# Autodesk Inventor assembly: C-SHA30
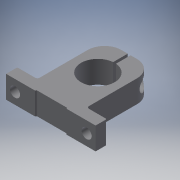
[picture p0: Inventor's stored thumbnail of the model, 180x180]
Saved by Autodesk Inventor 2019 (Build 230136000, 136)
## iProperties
Category: PARTsolutions
Company: MISUMI
Created: 2022-11
Part Number: C-SHA30
Catalog Web Link: www.cadenas.de
Description: C-SHA-Economy Shaft Supports - T-Shaped/Slit
Vendor: MISUMI
Document SubType Name: Assembly
Designer: psAdmin
Manufacturer: MISUMI
Mass: 49.6366 g
Surface Area: 148.895 cm^2
Volume: 49.6366 cm^3
Density: 1 g/cm^3
Title: C-SHA30
Author: Cadenas PARTsolutions
Comments: Economy Shaft Supports - T-Shaped/Slit
PSOL_IDENT_0: {$CADENAS_DATA/23d-libs/misumi/metric/02_shaft_supports/c_sha_asmtab.prj},167 {VTYP=3D},{STYP=ASSTAB
PSOL_IDENT_1: },{NB=C-SHA30},{LINA=C-SHA30},{NN=C-SHA},{DATE=04.10.2022 06:54:20},{GEOMDATE=23.04.2021 02:50:35},{
PSOL_IDENT_2: VERSION=},{LINEID=60},{WBVAR=},{WBNUMERIC=}  {NB=C-SHA30},{LINA=C-SHA30},{KT=DUMMY},{PN=C-SHA30},{TY
PSOL_IDENT_3: PE=C-SHA},{D=30},{H=42},{H1=70},{T=20},{L1=64},{DD=9.0},{E=21.0},{S=10},{R=15},{L=80},{B=28},{W=44},
PSOL_IDENT_4: {M=M6},{R2=2},{W2=2.5},{M3D=6},{M3D2=13.5},{M3D3=11},{M3D4=6.4},{LB=20},{PPATH=c_sha/c_sha_asmtpl.pr
PSOL_IDENT_5: j}
NB: C-SHA30
NN: C-SHA
NT: Economy Shaft Supports - T-Shaped/Slit
NBSYN: $PN.
LINA: C-SHA30
CATALOG: Misumi
PN: C-SHA30
D: 30
H: 42
H1: 70
T: 20
L1: 64
DD: 9
E: 21
S: 10
R: 15
L: 80
B: 28
W: 44
M: M6
SUPPLIER: MISUMI
ARTICLENO: C-SHA30
BOMINFO: C-SHA30
CREATOR: CADENAS GmbH
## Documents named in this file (3)
- e:\temp\worker_COMMON_2\temp\tmp_720_120_UZ9P2\format_0\C-SHA30.iam
- e:\temp\worker_COMMON_2\temp\tmp_720_120_UZ9P2\format_0\C-SHA30_b.ipt
- e:\temp\worker_COMMON_2\temp\tmp_720_120_UZ9P2\format_0\BOLT6-20.ipt
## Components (2 placed, 2 different names)
1. C-SHA30_b:1 — to_bolt_XY@1 <-> to_cp_XY@2, to_bolt_Z@1 <-> to_cp_Z@2, to_bolt_YZ@1 <-> to_cp_YZ@2
2. BOLT6-20:1 — to_bolt_XY@1 <-> to_cp_XY@2, to_bolt_Z@1 <-> to_cp_Z@2, to_bolt_YZ@1 <-> to_cp_YZ@2
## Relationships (3: Mate 2, Angle 1)
- to_bolt_XY@1 <-> to_cp_XY@2 [Mate]: C-SHA30_b:1 ↔ BOLT6-20:1
- to_bolt_Z@1 <-> to_cp_Z@2 [Mate]: C-SHA30_b:1 ↔ BOLT6-20:1
- to_bolt_YZ@1 <-> to_cp_YZ@2 [Angle]: C-SHA30_b:1 ↔ BOLT6-20:1
